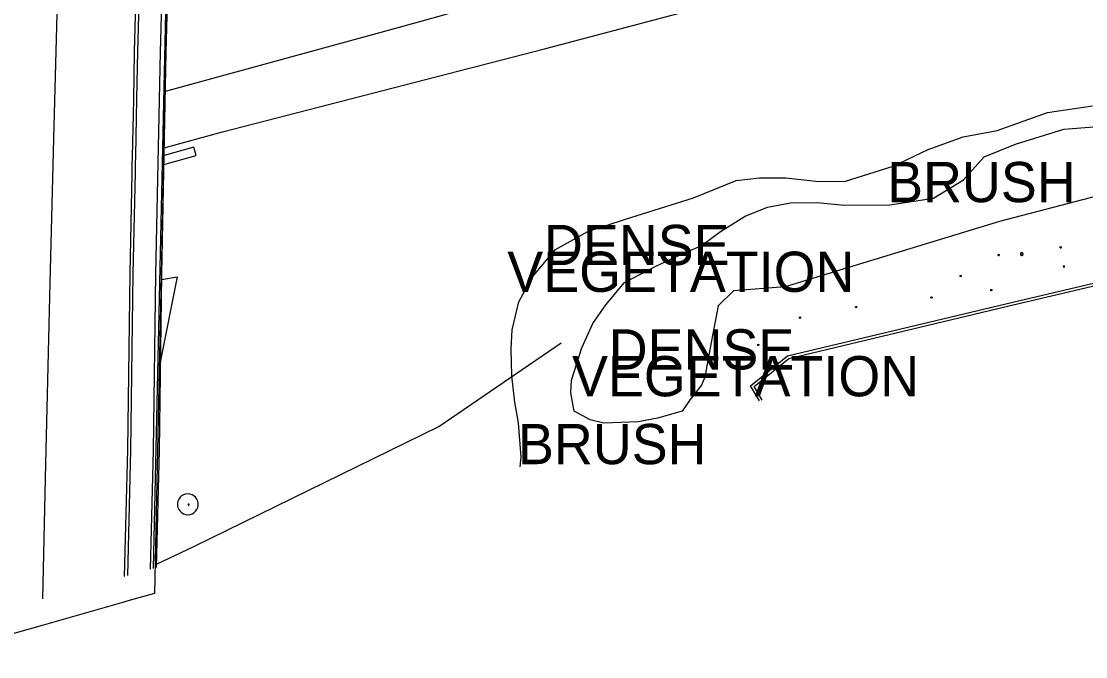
# Model space of a CAD drawing. Extents: x 2129547 to 2134906, y 657330 to 659734.
# Drawn here: x 2129756.3 to 2129941.3, y 657634.6 to 657745.2 of the extents above; entities that cross this region are included whole.
import ezdxf

# ---------------------------------------------------------------- set-up
doc = ezdxf.new("R2010")
doc.units = 0
for name, color, linetype in [('BR_X_SV_Deck_Top', 7, 'Continuous'), ('Default', 7, 'Continuous'), ('LT_X_Poles', 7, 'Continuous'), ('PM_X_CL_Double_Solid', 7, 'Continuous'), ('PM_X_Edge_Line', 7, 'Continuous'), ('PV_X_Curb', 7, 'Continuous'), ('PV_X_EOP2', 7, 'Continuous'), ('PV_X_Parking_Lot', 7, 'Continuous'), ('PV_X_Shoulder', 7, 'Continuous'), ('RD_X_Concrete_Barrier', 7, 'Continuous'), ('RD_X_Concrete_Pad', 7, 'Continuous'), ('RD_X_Fence', 7, 'Continuous'), ('RD_X_Misc_Items', 7, 'Continuous'), ('RD_X_Wall', 7, 'Continuous'), ('UT_X_Unknown_Cells', 7, 'Continuous'), ('VG_X_Cells', 7, 'Continuous'), ('VG_X_Shrub_Line_Lt', 7, 'Continuous'), ('VG_X_Text', 7, 'Continuous'), ('VG_X_Tree_Line_Lt', 7, 'Continuous')]:
    doc.layers.add(name, color=color, linetype=linetype)

# ---------------------------------------------------------------- blocks, each defined once
blk = doc.blocks.new('POINT_DISPLAY')
at = {"layer": 'Default'}
blk.add_line((0, 0), (0, 0), dxfattribs=at)

msp = doc.modelspace()

# ---------------------------------------------------------------- linework, layer by layer
at = {"layer": 'BR_X_SV_Deck_Top'}
msp.add_lwpolyline([(2129740.51, 657634.62), (2129741.87, 657685.89), (2129743.83, 657747.88), (2129748.02, 657912.97), (2129752.03, 657914.04), (2129752.54, 657914.17), (2129766.42, 657917.87), (2129780.56, 657921.96), (2129781.07, 657922.1), (2129785.55, 657923.4), (2129784.29, 657858.35), (2129782.53, 657795.25), (2129779.4, 657645.64), (2129774.6, 657644.27), (2129774.09, 657644.13), (2129759.88, 657640.06), (2129745.88, 657636.13), (2129745.37, 657635.99)], close=True, dxfattribs=at)
at = {"layer": 'LT_X_Poles'}
msp.add_lwpolyline([(2129937.54, 657702.69), (2129937.46, 657702.4), (2129937.58, 657702.4)], dxfattribs=at)
msp.add_circle((2129937.5, 657702.55), 0.065, dxfattribs=at)
at = {"layer": 'PM_X_CL_Double_Solid'}
msp.add_lwpolyline([(2129759.99, 657644.67), (2129760.54, 657668.18), (2129761.26, 657699.66), (2129761.98, 657727), (2129762.74, 657755.17), (2129763.33, 657784.8), (2129764.18, 657817.75), (2129764.97, 657850.67), (2129765.5, 657877.91), (2129766.42, 657917.87)], dxfattribs=at)
at = {"layer": 'PM_X_Edge_Line'}
msp.add_lwpolyline([(2129781.33, 657733.06), (2129822.4, 657744.28), (2129902.75, 657766.7), (2130016.9, 657798.42), (2130084.9, 657816.89), (2130135.24, 657830.94), (2130189.26, 657846.05), (2130240.42, 657859.85), (2130282.16, 657871.36), (2130318.23, 657881.32), (2130332.01, 657885.16), (2130356.78, 657892.02), (2130375.64, 657897.24), (2130413.2, 657907.59), (2130448.12, 657917.07), (2130481.79, 657926.44), (2130514.96, 657935.23), (2130533.56, 657939.51)], dxfattribs=at)
at = {"layer": 'PV_X_Curb'}
for points in [[(2129781.07, 657922.1), (2129779.72, 657870.26), (2129779.15, 657846.59), (2129779.12, 657845.02), (2129779.1, 657844.39), (2129778.87, 657834.64), (2129778.76, 657830.2), (2129777.97, 657796.3), (2129777.74, 657786.49), (2129777.69, 657784.74), (2129777.61, 657781.6), (2129777.27, 657769.18), (2129776.47, 657739.92), (2129776.3, 657731.69), (2129776.09, 657721.76), (2129776.07, 657720.45), (2129776.03, 657718.88), (2129775.67, 657701.29), (2129775.27, 657670.64), (2129774.71, 657648.74)], [(2129884.57, 657679.15), (2129883.01, 657681.79), (2129889.43, 657687), (2129928.6, 657696.31), (2129964.8, 657704.85), (2129999.37, 657713.02), (2130035.56, 657721.89), (2130065.94, 657728.85), (2130090.35, 657734.59), (2130113.79, 657740.05), (2130134.12, 657744.97), (2130136.89, 657741.78)]]:
    msp.add_lwpolyline(points, dxfattribs=at)
at = {"layer": 'PV_X_EOP2'}
for points in [[(2129781.33, 657733.06), (2129822.4, 657744.28), (2129902.75, 657766.7), (2130016.9, 657798.42), (2130084.9, 657816.89), (2130135.24, 657830.94), (2130189.26, 657846.05), (2130240.42, 657859.85), (2130282.16, 657871.36), (2130318.23, 657881.32), (2130332.01, 657885.16), (2130356.78, 657892.02), (2130375.64, 657897.24), (2130413.2, 657907.59), (2130448.12, 657917.07), (2130481.79, 657926.44), (2130514.96, 657935.23), (2130533.56, 657939.51)], [(2129774.21, 657648.6), (2129774.77, 657670.65), (2129775.17, 657701.3), (2129775.53, 657718.74), (2129775.56, 657720.31), (2129775.59, 657721.62), (2129775.8, 657731.55), (2129775.97, 657739.94), (2129776.77, 657769.04), (2129777.1, 657781.46), (2129777.19, 657784.6), (2129777.24, 657786.5), (2129777.47, 657796.16), (2129778.26, 657830.21), (2129778.36, 657834.5), (2129778.6, 657844.25), (2129778.61, 657844.88), (2129778.65, 657846.45), (2129779.22, 657870.27), (2129780.56, 657921.96)]]:
    msp.add_lwpolyline(points, dxfattribs=at)
at = {"layer": 'PV_X_Parking_Lot'}
msp.add_lwpolyline([(2129885.07, 657679.28), (2129883.66, 657681.67), (2129889.66, 657686.54), (2129928.71, 657695.83), (2129964.91, 657704.36), (2129999.49, 657712.53), (2130035.68, 657721.4), (2130066.05, 657728.37), (2130090.47, 657734.1), (2130113.9, 657739.56), (2130133.94, 657744.42), (2130136.35, 657741.64)], dxfattribs=at)
at = {"layer": 'PV_X_Shoulder'}
msp.add_lwpolyline([(2129781.12, 657723.15), (2129791.26, 657725.96), (2129847.2, 657740.42), (2129910.54, 657757.22), (2129956.62, 657769.85), (2130017.82, 657787.52), (2130067.36, 657801.54), (2130112.53, 657814.1), (2130168.41, 657829.75), (2130217.23, 657843.2), (2130272.91, 657858.21), (2130320.81, 657871.55), (2130356.56, 657881.59), (2130359.33, 657882.35), (2130366.22, 657884.23)], dxfattribs=at)
at = {"layer": 'RD_X_Concrete_Barrier'}
msp.add_lwpolyline([(2129781.06, 657720.29), (2129786.66, 657721.86), (2129786.25, 657723.3), (2129781.1, 657721.86)], dxfattribs=at)
at = {"layer": 'RD_X_Concrete_Pad'}
msp.add_lwpolyline([(2129785.21, 657662.97), (2129784.83, 657662.93), (2129784.47, 657662.81), (2129784.14, 657662.62), (2129783.86, 657662.37), (2129783.63, 657662.06), (2129783.48, 657661.71), (2129783.4, 657661.34), (2129783.4, 657660.96), (2129783.48, 657660.58), (2129783.64, 657660.24), (2129783.87, 657659.93), (2129784.15, 657659.68), (2129784.48, 657659.49), (2129784.84, 657659.37), (2129785.21, 657659.34), (2129785.59, 657659.38), (2129785.95, 657659.49), (2129786.28, 657659.69), (2129786.56, 657659.94), (2129786.79, 657660.25), (2129786.94, 657660.6), (2129787.02, 657660.97), (2129787.02, 657661.35), (2129786.94, 657661.72), (2129786.78, 657662.07), (2129786.55, 657662.38), (2129786.27, 657662.63), (2129785.94, 657662.82), (2129785.58, 657662.93)], close=True, dxfattribs=at)
at = {"layer": 'RD_X_Fence'}
msp.add_line((2129785.34, 657923.24), (2129779.16, 657649.97), dxfattribs=at)
msp.add_lwpolyline([(2129779.76, 657650.72), (2129786.26, 657653.8), (2129828.86, 657674.67), (2129850.09, 657689.26)], dxfattribs=at)
at = {"layer": 'RD_X_Misc_Items'}
msp.add_lwpolyline([(2129780.66, 657700.25), (2129783.34, 657700.72), (2129780.48, 657686.18)], dxfattribs=at)
at = {"layer": 'RD_X_Wall'}
for points in [[(2129779.75, 657650.14), (2129780.27, 657670.55), (2129780.67, 657701.2), (2129781.47, 657739.8), (2129782.74, 657786.36), (2129783.76, 657830.08), (2129784.72, 657870.13), (2129786.1, 657923.55), (2129786.14, 657924.85)], [(2129778.74, 657649.86), (2129779.27, 657670.56), (2129779.67, 657701.22), (2129780.47, 657739.83), (2129781.74, 657786.39), (2129782.76, 657830.1), (2129783.72, 657870.16), (2129785.1, 657923.27)]]:
    msp.add_lwpolyline(points, dxfattribs=at)
at = {"layer": 'UT_X_Unknown_Cells'}
for p, q in [((2129785.27, 657661.13), (2129785.27, 657661.07)), ((2129785.32, 657661.13), (2129785.32, 657661.07))]:
    msp.add_line(p, q, dxfattribs=at)
msp.add_lwpolyline([(2129785.35, 657661.05), (2129785.35, 657661.13), (2129785.38, 657661.05), (2129785.41, 657661.13), (2129785.41, 657661.05)], dxfattribs=at)
for centre, radius, start, end in [((2129785.34, 657661.09), 0.1, 160.0169, 200.0392), ((2129785.34, 657661.09), 0.1, 100.0806, 140.0721), ((2129785.34, 657661.09), 0.1, 220.0577, 260.0473), ((2129785.3, 657661.08), 0.0279, 205.1924, 334.8076), ((2129785.34, 657661.09), 0.1, 40.0577, 80.1061), ((2129785.34, 657661.09), 0.1, 280.0114, 320.0264), ((2129785.34, 657661.09), 0.1, 340.0169, 20.0392)]:
    msp.add_arc(centre, radius, start, end, dxfattribs=at)
at = {"layer": 'VG_X_Cells'}
for points in [[(2129936.95, 657705.94), (2129936.98, 657705.98), (2129937, 657705.93), (2129937.06, 657705.93), (2129937.04, 657705.88), (2129937.09, 657705.85), (2129937.05, 657705.82), (2129937.06, 657705.77), (2129937.02, 657705.77), (2129937, 657705.73), (2129936.98, 657705.76), (2129936.95, 657705.72), (2129936.93, 657705.77), (2129936.88, 657705.75), (2129936.89, 657705.79), (2129936.85, 657705.79), (2129936.87, 657705.83), (2129936.83, 657705.86), (2129936.87, 657705.87), (2129936.84, 657705.91), (2129936.88, 657705.9), (2129936.88, 657705.96), (2129936.92, 657705.93), (2129936.93, 657705.98), (2129936.95, 657705.94)], [(2129926.17, 657704.62), (2129926.2, 657704.66), (2129926.22, 657704.6), (2129926.28, 657704.61), (2129926.26, 657704.56), (2129926.31, 657704.53), (2129926.27, 657704.5), (2129926.28, 657704.45), (2129926.24, 657704.45), (2129926.22, 657704.41), (2129926.2, 657704.44), (2129926.17, 657704.4), (2129926.15, 657704.45), (2129926.1, 657704.42), (2129926.11, 657704.47), (2129926.07, 657704.47), (2129926.09, 657704.51), (2129926.05, 657704.54), (2129926.09, 657704.55), (2129926.06, 657704.59), (2129926.1, 657704.58), (2129926.1, 657704.64), (2129926.14, 657704.61), (2129926.15, 657704.66), (2129926.17, 657704.62)], [(2129919.54, 657700.98), (2129919.57, 657701.02), (2129919.59, 657700.96), (2129919.64, 657700.97), (2129919.63, 657700.92), (2129919.67, 657700.89), (2129919.63, 657700.86), (2129919.64, 657700.81), (2129919.6, 657700.81), (2129919.59, 657700.77), (2129919.57, 657700.8), (2129919.53, 657700.76), (2129919.51, 657700.81), (2129919.46, 657700.78), (2129919.47, 657700.83), (2129919.43, 657700.83), (2129919.45, 657700.87), (2129919.41, 657700.89), (2129919.45, 657700.91), (2129919.42, 657700.95), (2129919.47, 657700.94), (2129919.47, 657700.99), (2129919.5, 657700.97), (2129919.51, 657701.02), (2129919.54, 657700.98)], [(2129924.86, 657698.51), (2129924.89, 657698.55), (2129924.91, 657698.49), (2129924.97, 657698.5), (2129924.95, 657698.45), (2129925, 657698.42), (2129924.96, 657698.39), (2129924.97, 657698.34), (2129924.93, 657698.34), (2129924.91, 657698.3), (2129924.89, 657698.33), (2129924.86, 657698.29), (2129924.84, 657698.34), (2129924.79, 657698.31), (2129924.8, 657698.36), (2129924.76, 657698.36), (2129924.78, 657698.4), (2129924.74, 657698.42), (2129924.78, 657698.44), (2129924.75, 657698.48), (2129924.79, 657698.47), (2129924.79, 657698.52), (2129924.83, 657698.5), (2129924.84, 657698.55), (2129924.86, 657698.51)], [(2129914.49, 657697.23), (2129914.52, 657697.27), (2129914.54, 657697.21), (2129914.59, 657697.22), (2129914.58, 657697.17), (2129914.62, 657697.14), (2129914.58, 657697.11), (2129914.59, 657697.06), (2129914.56, 657697.06), (2129914.54, 657697.02), (2129914.52, 657697.05), (2129914.49, 657697.01), (2129914.46, 657697.06), (2129914.41, 657697.03), (2129914.42, 657697.08), (2129914.38, 657697.08), (2129914.41, 657697.12), (2129914.37, 657697.14), (2129914.4, 657697.16), (2129914.37, 657697.2), (2129914.42, 657697.19), (2129914.42, 657697.24), (2129914.46, 657697.22), (2129914.47, 657697.27), (2129914.49, 657697.23)], [(2129901.37, 657695.55), (2129901.4, 657695.59), (2129901.42, 657695.54), (2129901.48, 657695.55), (2129901.46, 657695.5), (2129901.51, 657695.47), (2129901.47, 657695.43), (2129901.48, 657695.38), (2129901.44, 657695.39), (2129901.43, 657695.34), (2129901.4, 657695.38), (2129901.37, 657695.33), (2129901.35, 657695.38), (2129901.3, 657695.36), (2129901.31, 657695.4), (2129901.27, 657695.4), (2129901.29, 657695.44), (2129901.25, 657695.47), (2129901.29, 657695.48), (2129901.26, 657695.52), (2129901.31, 657695.52), (2129901.3, 657695.57), (2129901.34, 657695.54), (2129901.35, 657695.59), (2129901.37, 657695.55)], [(2129891.63, 657693.72), (2129891.66, 657693.75), (2129891.68, 657693.7), (2129891.73, 657693.71), (2129891.72, 657693.66), (2129891.76, 657693.63), (2129891.72, 657693.59), (2129891.73, 657693.55), (2129891.7, 657693.55), (2129891.68, 657693.51), (2129891.66, 657693.54), (2129891.63, 657693.5), (2129891.6, 657693.54), (2129891.55, 657693.52), (2129891.56, 657693.57), (2129891.52, 657693.57), (2129891.55, 657693.61), (2129891.51, 657693.63), (2129891.54, 657693.65), (2129891.51, 657693.69), (2129891.56, 657693.68), (2129891.56, 657693.73), (2129891.6, 657693.7), (2129891.61, 657693.75), (2129891.63, 657693.72)], [(2129884.36, 657688.98), (2129884.39, 657689.01), (2129884.41, 657688.96), (2129884.47, 657688.97), (2129884.45, 657688.92), (2129884.5, 657688.89), (2129884.45, 657688.85), (2129884.47, 657688.81), (2129884.43, 657688.81), (2129884.41, 657688.77), (2129884.39, 657688.8), (2129884.36, 657688.76), (2129884.34, 657688.8), (2129884.28, 657688.78), (2129884.29, 657688.83), (2129884.25, 657688.82), (2129884.28, 657688.86), (2129884.24, 657688.89), (2129884.28, 657688.91), (2129884.25, 657688.95), (2129884.29, 657688.94), (2129884.29, 657688.99), (2129884.33, 657688.96), (2129884.34, 657689.01), (2129884.36, 657688.98)]]:
    msp.add_lwpolyline(points, dxfattribs=at)
for centre, radius in [((2129936.96, 657705.85), 0.0115), ((2129926.18, 657704.53), 0.0115), ((2129930.18, 657704.68), 0.012), ((2129919.54, 657700.89), 0.0115), ((2129924.87, 657698.42), 0.0115), ((2129914.49, 657697.14), 0.0115), ((2129901.38, 657695.46), 0.0115), ((2129891.63, 657693.63), 0.0115), ((2129884.36, 657688.89), 0.0115)]:
    msp.add_circle(centre, radius, dxfattribs=at)
for centre, radius, start, end in [((2129930.01, 657704.77), 0.0735, 39.0625, 279.5412), ((2129930.04, 657704.6), 0.0987, 96.1722, 320.5737), ((2129930.13, 657704.84), 0.0658, 354.0047, 205.9741), ((2129930.23, 657704.55), 0.114, 184.9476, 19.4572), ((2129930.27, 657704.82), 0.0776, 323.83, 165.0376), ((2129930.35, 657704.68), 0.0957, 259.1453, 101.4596)]:
    msp.add_arc(centre, radius, start, end, dxfattribs=at)
at = {"layer": 'VG_X_Shrub_Line_Lt'}
msp.add_lwpolyline([(2129842.99, 657667.64), (2129843.14, 657669.34), (2129842.68, 657675.3), (2129842.08, 657678.9), (2129841.56, 657683.53), (2129841.42, 657688.18), (2129841.62, 657691.53), (2129842.75, 657696.38), (2129845.09, 657700.7), (2129849.15, 657705.47), (2129854.74, 657708.64), (2129861.31, 657710.78), (2129873.14, 657714.47), (2129880.53, 657717.52), (2129884.57, 657717.97), (2129889.15, 657717.97), (2129894.36, 657717.4), (2129899.34, 657717.32), (2129907.85, 657720.01), (2129913.88, 657722.9), (2129919.98, 657725.09), (2129925.93, 657726.18), (2129934.65, 657729.33), (2129942.48, 657730.49)], dxfattribs=at)
at = {"layer": 'VG_X_Tree_Line_Lt'}
for points in [[(2130030.94, 657735.91), (2130003.92, 657729.15), (2129962.08, 657719.69), (2129926.29, 657710.37), (2129889.05, 657698.98), (2129880.08, 657698.29), (2129877.39, 657695.71), (2129876.19, 657689.3), (2129875.73, 657686.81), (2129875.09, 657683.27), (2129874.5, 657681.88), (2129872.51, 657679.36), (2129871.15, 657677.36)], [(2129871.15, 657677.36), (2129866.84, 657676.14), (2129863.49, 657675.51), (2129857.54, 657675.25), (2129855.16, 657675.84), (2129852.38, 657677.35), (2129851.78, 657680.52), (2129851.91, 657682.74), (2129853.69, 657688.4), (2129855.59, 657692.61), (2129857.87, 657695.83), (2129861.1, 657699.73), (2129866.66, 657702.66), (2129871.97, 657705.09), (2129874.43, 657706.12), (2129877.82, 657708.61), (2129882.12, 657711.26), (2129885.95, 657712.84), (2129889.96, 657713.63), (2129894.63, 657713.66), (2129899.3, 657713.2), (2129907.27, 657713.28), (2129914.86, 657714.43), (2129920.03, 657717.62), (2129923.63, 657721.6), (2129929.08, 657723.84), (2129937.49, 657726.43), (2129942.68, 657726.85)]]:
    msp.add_lwpolyline(points, dxfattribs=at)

# ---------------------------------------------------------------- block references
at = {"layer": 'UT_X_Unknown_Cells', "xscale": 3.9370000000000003, "yscale": 3.9370000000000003}
msp.add_blockref('POINT_DISPLAY', (2129785.34, 657661.09), dxfattribs=at)

# ---------------------------------------------------------------- texts
at = {"layer": 'VG_X_Text'}
for s, p in [('BRUSH', (2129906.78, 657713.72)), ('DENSE', (2129847.13, 657702.77)), ('VEGETATION', (2129840.75, 657698.11)), ('DENSE', (2129858.38, 657684.6)), ('VEGETATION', (2129852, 657679.94)), ('BRUSH', (2129842.61, 657668.13))]:
    msp.add_text(s, height=7, dxfattribs=at).set_placement(p)

doc.saveas('drawing.dxf')
